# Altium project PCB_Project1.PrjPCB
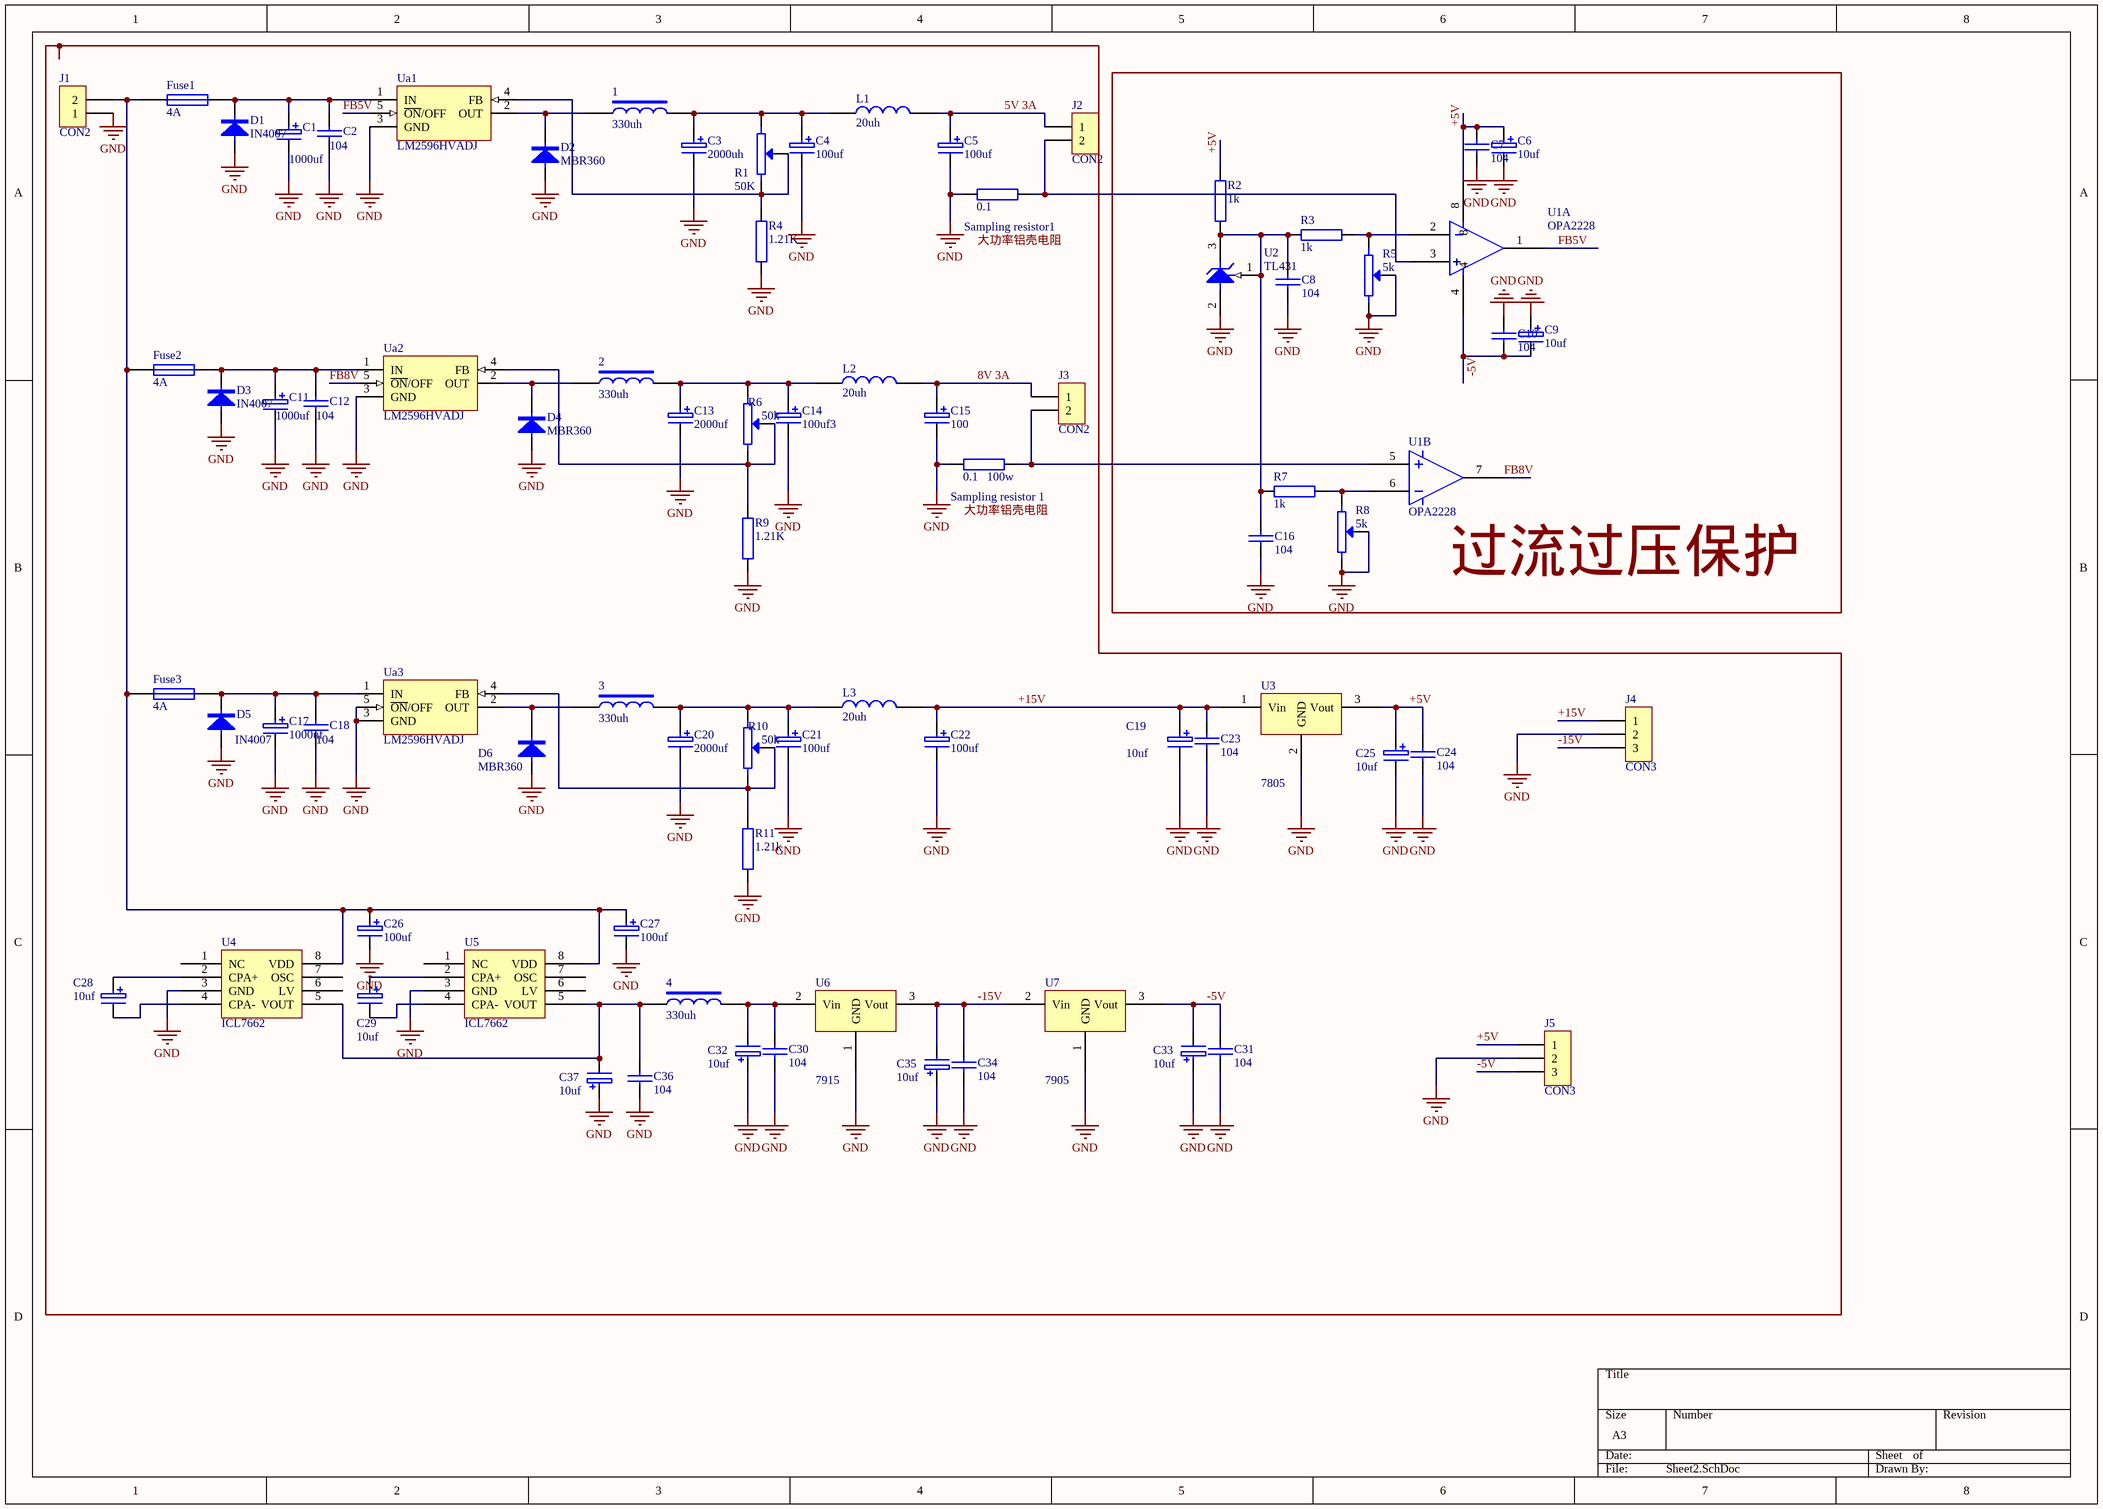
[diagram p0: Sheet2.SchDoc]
1 sheet, 81 parts. Net scope: global (net labels, ports and power ports of the same name join across sheets).
Board file: PCB2.PcbDoc

## Sheet Sheet2.SchDoc
size A3

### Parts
1  330uh  [L]
2  330uh  [L]
3  330uh  [L]
4  330uh  [L]
C1  1000uf  [RB2]
C2  104  [RAD0.2]
C3  2000uh  [RB3]
C4  100uf  [RB1]
C5  100uf  [RB1]
C6  10uf  [RB1]
C7  104  [RAD0.15]
C8  104  [RAD0.15]
C9  10uf  [RB1]
C10  104  [RAD0.15]
C11  1000uf  [RB2]
C12  104  [RAD0.2]
C13  2000uf  [RB3]
C14  100uf3  [RB1]
C15  100  [RB1]
C16  104  [RAD0.15]
C17  1000uf  [RB2]
C18  104  [RAD0.2]
C19  10uf  [RB1]
C20  2000uf  [RB3]
C21  100uf  [RB1]
C22  100uf  [RB1]
C23  104  [RAD0.15]
C24  104  [RAD0.15]
C25  10uf  [RB1]
C26  100uf  [RB1]
C27  100uf  [RB1]
C28  10uf  [RB1]
C29  10uf  [RB1]
C30  104  [RAD0.15]
C31  104  [RAD0.15]
C32  10uf  [RB1]
C33  10uf  [RB1]
C34  104  [RAD0.15]
C35  10uf  [RB1]
C36  104  [RAD0.15]
C37  10uf  [RB1]
D1  IN4007  [DIODE0.4]
D2  MBR360  [DIODE0.2]
D3  IN4007  [DIODE0.4]
D4  MBR360  [DIODE0.2]
D5  IN4007  [DIODE0.4]
D6  MBR360  [DIODE0.2]
Fuse1  4A  [RAD0.5]
Fuse2  4A  [RAD0.5]
Fuse3  4A  [RAD0.5]
J1  CON2  [BCON2]
J2  CON2  [BCON2]
J3  CON2  [BCON2]
J4  CON3  [BCON3]
J5  CON3  [sip-3]
L1  20uh  [LHF440]
L2  20uh  [LHF440]
L3  20uh  [LHF440]
R1  50K  [VR5]
R2  1k  [AXIAL0.3]
R3  1k  [AXIAL0.3]
R4  1.21K  [AXIAL0.3]
R5  5k  [VR5]
R6  50k  [VR5]
R7  1k  [AXIAL0.3]
R8  5k  [VR5]
R9  1.21K  [AXIAL0.3]
R10  50k  [VR5]
R11  1.21k  [AXIAL0.3]
Sampling_resistor1  0.1  [AXIAL1.0]
Sampling_resistor_1  0.1   100w  [AXIAL1.0]
U1  OPA2228  [DIP-8]  (parts A,B of 2)
U2  TL431  [TO92B]
U3  7805  [TO257V]
U4  ICL7662  [DIP-8]
U5  ICL7662  [DIP-8]
U6  7915  [TO257V]
U7  7905  [TO257V]
Ua1  LM2596HVADJ  [SIP-5]
Ua2  LM2596HVADJ  [SIP-5]
Ua3  LM2596HVADJ  [SIP-5]

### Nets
GND: C1.2 C2.2 C3.2 C4.2 C5.2 C6.2 C7.2 C8.2 C9.1 C10.1 C11.2 C12.2 C13.2 C14.2 C15.2 C16.2 C17.2 C18.2 C19.2 C20.2 C21.2 C22.2 C23.2 C24.2 C25.2 C26.2 C27.2 C30.2 C31.2 C32.1 C33.1 C34.2 C35.1 C36.2 C37.1 D1.1 D2.1 D3.1 D4.1 D5.1 D6.1 J1.1 J4.2 J5.2 R4.1 R5.2(VT) R5.3 R8.2(VT) R8.3 R9.1 R11.1 Sampling_resistor1.2 Sampling_resistor_1.2 U2.2(A) U3.2(GND) U4.3(GND) U5.3(GND) U6.1(GND) U7.1(GND) Ua1.3(GND) Ua2.3(GND) Ua3.3(GND) Ua3.5(~{ON}/OFF)
5V 3A: C5.1 J2.1 L1.2
8V 3A: C15.1 J3.1 L2.2
+5V: C6.1 C7.1 C24.1 C25.1 J5.1 R2.2 U1.8 U3.3(Vout)
+15V: C19.1 C22.1 C23.1 J4.1 L3.2 U3.1(Vin)
-5V: C9.2 C10.2 C31.1 C33.2 J5.3 U1.4 U7.3(Vout)
-15V: C34.1 C35.2 J4.3 U6.3(Vout) U7.2(Vin)
FB5V: U1.1(+) Ua1.5(~{ON}/OFF)
FB8V: U1.7 Ua2.5(~{ON}/OFF)
Net1_1: 1.1 D2.2 Ua1.2(OUT)
Net1_2: 1.2 C3.1 C4.1 L1.1 R1.1
Net2_1: 2.1 D4.2 Ua2.2(OUT)
Net2_2: 2.2 C13.1 C14.1 L2.1 R6.1
Net3_1: 3.1 D6.2 Ua3.2(OUT)
Net3_2: 3.2 C20.1 C21.1 L3.1 R10.1
Net4_1: 4.1 C36.1 C37.2 U4.5(VOUT) U5.5(VOUT)
Net4_2: 4.2 C30.1 C32.2 U6.2(Vin)
NetC1_1: C1.1 C2.1 D1.2 Fuse1.1 Ua1.1(IN)
NetC8_1: C8.1 C16.1 R2.1 R3.1 R7.1 U2.1(REF) U2.3(K)
NetC11_1: C11.1 C12.1 D3.2 Fuse2.1 Ua2.1(IN)
NetC17_1: C17.1 C18.1 D5.2 Fuse3.1 Ua3.1(IN)
NetC26_1: C26.1 C27.1 Fuse1.2 Fuse2.2 Fuse3.2 J1.2 U4.8(VDD) U5.8(VDD)
NetC28_1: C28.1 U4.2(CPA+)
NetC28_2: C28.2 U4.4(CPA-)
NetC29_1: C29.1 U5.2(CPA+)
NetC29_2: C29.2 U5.4(CPA-)
NetJ2_2: J2.2 Sampling_resistor1.1 U1.3
NetJ3_2: J3.2 Sampling_resistor_1.1 U1.5
NetR1_2: R1.2(VT) R1.3 R4.2 Ua1.4(FB)
NetR3_2: R3.2 R5.1 U1.2(-)
NetR6_2: R6.2(VT) R6.3 R9.2 Ua2.4(FB)
NetR7_2: R7.2 R8.1 U1.6
NetR10_2: R10.2(VT) R10.3 R11.2 Ua3.4(FB)

Not connected (* = marked no-connect by the designer): U4 1(NC) 6(LV) 7(OSC); U5 1(NC) 6(LV) 7(OSC)

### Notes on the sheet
- Labels drawn without touching a wire or pin: 大功率铝壳电阻, 过流过压保护

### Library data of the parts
1-4 = INDUCTOR2
C1 C3-C6 C9 C11 C13-C15 C17 C19-C22 C25-C29 C32 C33 C35 C37 = CAP3
C2 C7 C8 C10 C12 C16 C18 C23 C24 C30 C31 C34 C36 = CAP1
D1-D6 = DIODE
Fuse1-Fuse3 = FUSE1: Fuse
J1-J3 = CON2: Connector
J4 J5 = CON3: Connector
L1-L3 = INDUCTOR
R1 R5 R6 R8 R10 = RPOT2: Potentiometer
R2-R4 R7 R9 R11 Sampling_resistor1 Sampling_resistor_1 = RES
U1 = NE5532
U2 = TL431: Programmable Voltage Reference
U3 = 78**
U6 U7 = 79**
Ua1-Ua3 = LM2596T-5.0: Simple Switcher Power Converter 150 kHz 3A Step Down Voltage Regulator; PackageDocument: 2000; Note: Tab is connected to GND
